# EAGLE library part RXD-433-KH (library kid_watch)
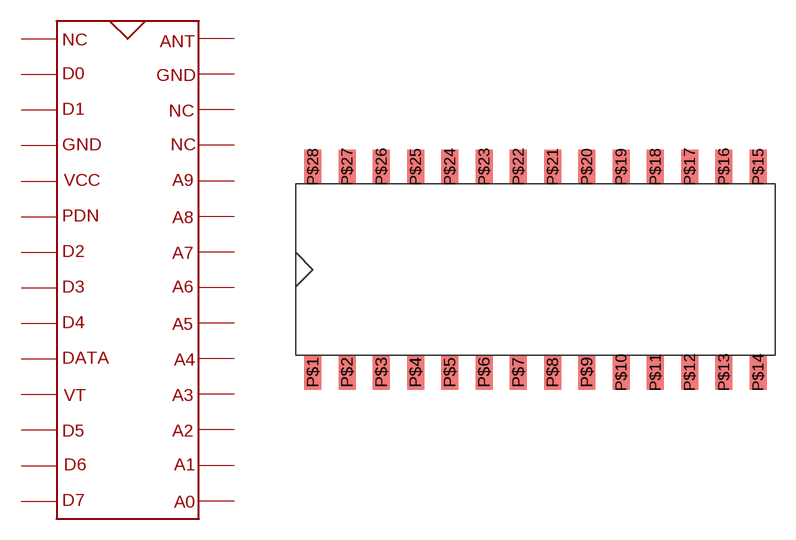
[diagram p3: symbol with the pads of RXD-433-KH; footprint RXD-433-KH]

Designator prefix -

## RXD-433-KH  [RXD-433-KH]
P$1  P$1
P$2  P$2
P$3  P$3
P$4  P$4
P$5  P$5
P$6  P$6
P$7  P$7
P$8  P$8
P$9  P$9
P$10  P$10
P$11  P$11
P$12  P$12
P$13  P$13
P$14  P$14
P$15  P$15
P$16  P$16
P$17  P$17
P$18  P$18
P$19  P$19
P$20  P$20
P$21  P$21
P$22  P$22
P$23  P$23
P$24  P$24
P$25  P$25
P$26  P$26
P$27  P$27
P$28  P$28

## Footprint RXD-433-KH (pad centres in mm)
smd 1.27 x 2.54: P$1 0,0; P$2 2.54,0; P$3 5.08,0; P$4 7.62,0; P$5 10.16,0; P$6 12.7,0; P$7 15.24,0; P$8 17.78,0; P$9 20.32,0; P$10 22.86,0; P$11 25.4,0; P$12 27.94,0; P$13 30.48,0; P$14 33.02,0; P$15 33.02,15.24; P$16 30.48,15.24; P$17 27.94,15.24; P$18 25.4,15.24; P$19 22.86,15.24; P$20 20.32,15.24; P$21 17.78,15.24; P$22 15.24,15.24; P$23 12.7,15.24; P$24 10.16,15.24; P$25 7.62,15.24; P$26 5.08,15.24; P$27 2.54,15.24; P$28 0,15.24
